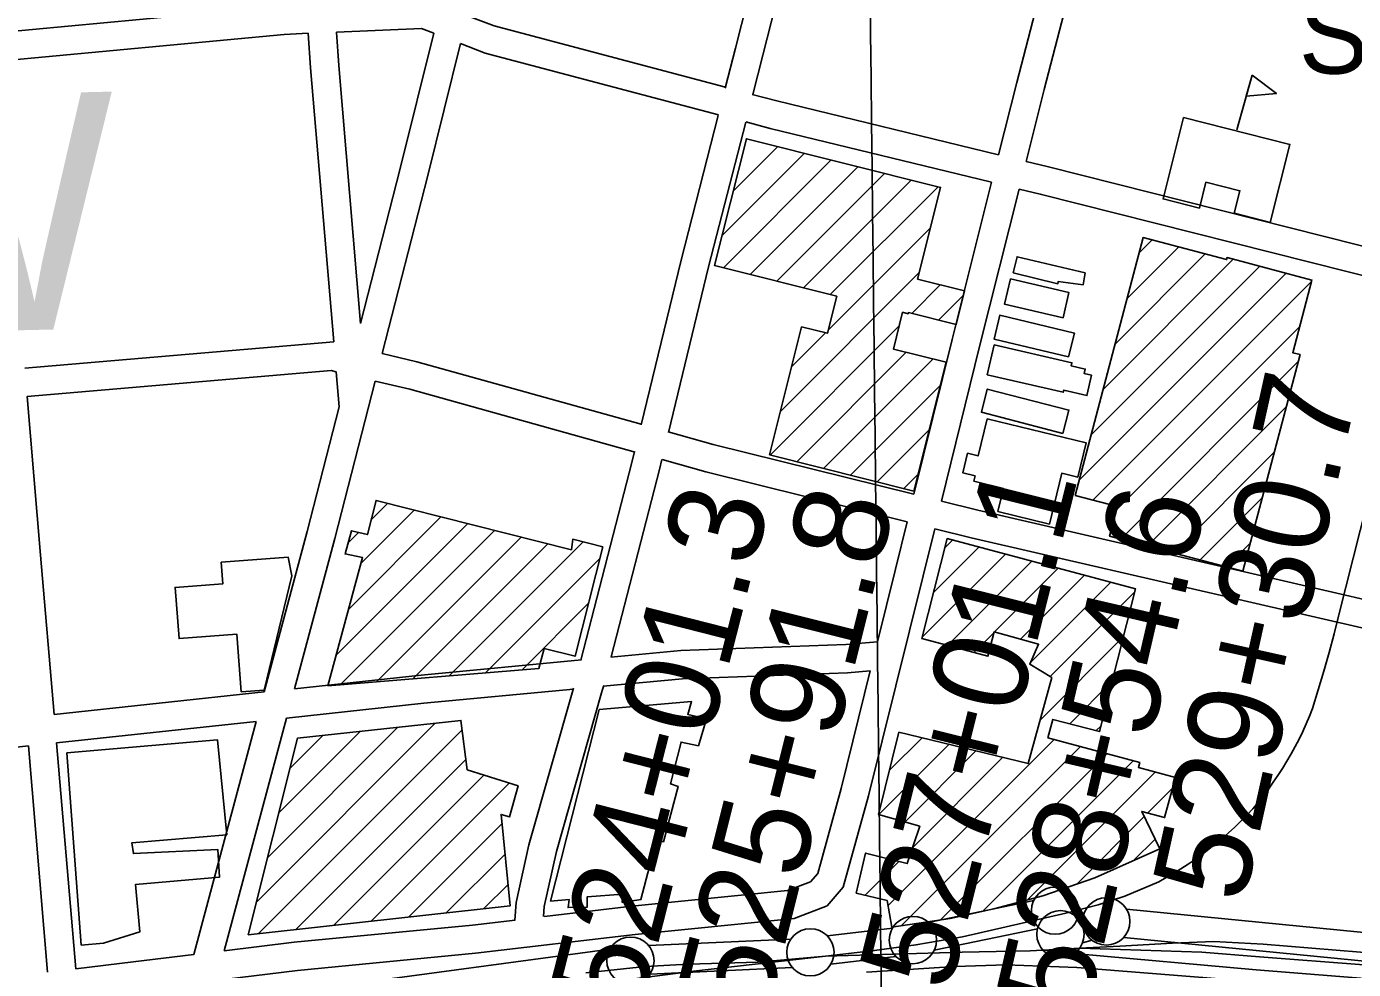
# Model space of a CAD drawing. Extents: x 3677843 to 3715951, y 511991 to 537744.
# Drawn here: x 3686291 to 3687695, y 533993 to 534990 of the extents above; entities that cross this region are included whole.
import ezdxf

# ---------------------------------------------------------------- set-up
doc = ezdxf.new("R2010")
doc.units = 0
for name, color, linetype in [('V-BLDG-IDEN', 7, 'Continuous'), ('V-BLDG-OTLN', 7, 'Continuous'), ('V-GRID-MAJR', 7, 'Continuous'), ('V-RAIL-TRAK', 7, 'Continuous'), ('V-ROAD-CNTR', 7, 'Continuous'), ('V-SURV-IDEN', 7, 'Continuous'), ('V-SURV-LINE', 7, 'Continuous'), ('V-TOPO-GNAM-IDEN', 7, 'Continuous')]:
    doc.layers.add(name, color=color, linetype=linetype)

msp = doc.modelspace()

# ---------------------------------------------------------------- linework, layer by layer
at = {"layer": 'V-BLDG-OTLN'}
for p, q in [((3687571.2611612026, 534880.8787085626), (3687587.2901291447, 534938.6975929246)), ((3687026.824611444, 534769.2415094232), (3687113.8029269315, 534856.2198249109)), ((3687038.658142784, 534816.430379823), (3687085.5365229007, 534863.3087599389)), ((3687028.0542040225, 534735.1157629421), (3687142.0693309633, 534849.1308898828)), ((3687056.3208279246, 534728.027047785), (3687170.335734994, 534842.0419548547)), ((3687084.5874518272, 534720.9383326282), (3687198.602139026, 534834.9530198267)), ((3687112.8540757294, 534713.8496174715), (3687226.868543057, 534827.8640847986)), ((3687141.120699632, 534706.7609023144), (3687255.1349470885, 534820.7751497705)), ((3687138.9757143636, 534669.2605779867), (3687247.1347835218, 534777.4196471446)), ((3687455.049351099, 534702.4915022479), (3687509.7499039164, 534757.192055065)), ((3687467.713929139, 534750.511419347), (3687481.773059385, 534764.570549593)), ((3687429.7201950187, 534606.4516680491), (3687567.4057363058, 534744.1372093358)), ((3687442.384773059, 534654.4715851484), (3687537.7267484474, 534749.8135605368)), ((3687088.422775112, 534583.3522996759), (3687235.298246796, 534730.2277713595)), ((3687404.3910389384, 534510.4118338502), (3687623.3595334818, 534729.3803283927)), ((3687417.0556169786, 534558.4317509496), (3687595.3826348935, 534736.7587688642)), ((3687227.3668848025, 534686.9410703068), (3687257.529902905, 534717.1040884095)), ((3687418.8377047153, 534489.5031605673), (3687650.4104398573, 534721.0758957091)), ((3687255.631909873, 534679.8507563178), (3687282.274512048, 534706.4933584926)), ((3687077.604196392, 534537.1783818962), (3687214.0337889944, 534673.6079744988)), ((3687444.0039970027, 534479.3141137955), (3687637.7455328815, 534673.0556496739)), ((3687100.257409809, 534630.5422734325), (3687136.058035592, 534666.342899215)), ((3687105.870501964, 534530.0893484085), (3687221.57390119, 534645.7927476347)), ((3687134.1368075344, 534523.0003149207), (3687249.839914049, 534638.7034214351)), ((3687448.3670056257, 534448.321783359), (3687636.120581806, 534636.0753595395)), ((3687162.403113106, 534515.9112814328), (3687257.596158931, 534611.1043272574)), ((3687476.3438063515, 534440.9432450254), (3687623.455619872, 534588.0550585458)), ((3687190.669418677, 534508.8222479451), (3687245.7617155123, 534563.91454478)), ((3687504.3206070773, 534433.5647066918), (3687610.790657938, 534540.0347575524)), ((3687218.935724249, 534501.733214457), (3687233.927272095, 534516.7247623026)), ((3686655.494295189, 534468.6218712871), (3686672.9273962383, 534486.0549723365)), ((3687532.2974078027, 534426.1861683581), (3687598.125696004, 534492.014456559)), ((3686631.57673944, 534373.993637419), (3686729.3770926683, 534471.7939906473)), ((3686644.7059794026, 534422.4782164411), (3686701.1522444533, 534478.924481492)), ((3686618.4474994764, 534325.5090583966), (3686757.601940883, 534464.6634998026)), ((3686622.643948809, 534294.3501686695), (3686785.826789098, 534457.5330089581)), ((3686631.1656525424, 534444.2932286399), (3686642.1418836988, 534455.2694597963)), ((3686661.1340708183, 534297.4849516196), (3686814.051637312, 534450.4025181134)), ((3686699.6241928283, 534300.6197345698), (3686842.276485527, 534443.2720272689)), ((3686738.1143148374, 534303.75451752), (3686879.653586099, 534445.2937887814)), ((3687262.1979648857, 534438.9294379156), (3687270.4722623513, 534447.2037353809)), ((3687560.2742085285, 534418.8076300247), (3687585.4607340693, 534443.9941555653)), ((3687238.123527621, 534344.1443225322), (3687326.3321141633, 534432.3529090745)), ((3687250.160746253, 534391.536880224), (3687298.4021882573, 534439.7783222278)), ((3686776.604436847, 534306.8893004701), (3686897.5312080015, 534427.8160716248)), ((3687265.2681762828, 534335.9336321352), (3687354.26204007, 534424.9274959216)), ((3687314.8076947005, 534350.1178114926), (3687382.191965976, 534417.5020827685)), ((3687342.4462611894, 534342.4010389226), (3687410.121891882, 534410.0766696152)), ((3687352.73641699, 534317.3358556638), (3687438.0518177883, 534402.6512564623)), ((3687373.709564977, 534302.9536645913), (3687463.089273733, 534392.333373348)), ((3686815.0945588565, 534310.0240834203), (3686885.481727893, 534380.4112524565)), ((3687293.086713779, 534328.3968305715), (3687314.3655457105, 534349.6756625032)), ((3687363.052896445, 534256.9416570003), (3687451.2570623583, 534345.1458229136)), ((3687394.396183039, 534252.9296045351), (3687439.424850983, 534297.9582724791)), ((3686534.2363084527, 534064.5211720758), (3686723.2871094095, 534253.5719730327)), ((3686536.0221206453, 534030.9516452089), (3686751.7551807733, 534246.684705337)), ((3686546.080325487, 534111.7205281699), (3686683.6508002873, 534249.29100297)), ((3687422.5455621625, 534245.7236445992), (3687427.5926396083, 534250.7707220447)), ((3686557.924342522, 534158.9198842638), (3686644.014491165, 534245.0100329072)), ((3686569.7683595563, 534206.1192403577), (3686604.3781820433, 534240.7290628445)), ((3687202.273724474, 534060.8071459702), (3687377.85077788, 534236.3841993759)), ((3687203.840381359, 534203.7951590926), (3687238.1893897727, 534238.1441675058)), ((3687192.4082789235, 534157.0077175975), (3687266.6264344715, 534231.2258731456)), ((3687216.1218276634, 534039.2999101), (3687405.709381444, 534228.8874638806)), ((3687219.8970534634, 534149.1411530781), (3687295.0634791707, 534224.3075787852)), ((3687257.861634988, 534045.6843783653), (3687433.567985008, 534221.390728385)), ((3686575.8080925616, 534035.3822780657), (3686755.7368139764, 534215.3109994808)), ((3687228.352094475, 534122.2408550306), (3687323.5005238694, 534217.3892844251)), ((3687302.1520817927, 534054.6194861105), (3687461.4265885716, 534213.8939928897)), ((3686615.594064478, 534039.8129109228), (3686774.577562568, 534198.7964090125)), ((3686655.3800363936, 534044.2435437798), (3686801.3983208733, 534190.2618282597)), ((3687349.7251066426, 534066.837171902), (3687484.8869513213, 534201.9990165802)), ((3687476.931508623, 534158.6882348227), (3687503.1022089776, 534184.8589351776)), ((3686801.2301170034, 534154.7382853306), (3686801.947162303, 534155.4553306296)), ((3687401.800874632, 534083.5576008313), (3687473.219150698, 534154.9758768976)), ((3686695.1660083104, 534048.674176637), (3686793.8609017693, 534147.369070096)), ((3687461.910575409, 534108.3119625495), (3687484.697111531, 534131.0984986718)), ((3686734.9519802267, 534053.1048094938), (3686797.117988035, 534115.2708173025)), ((3687177.9519670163, 534071.8407275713), (3687213.5165841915, 534107.4053447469)), ((3686774.737952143, 534057.5354423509), (3686800.375074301, 534083.1725645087))]:
    msp.add_line(p, q, dxfattribs=at)
for points in [[(3687587.2901291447, 534938.6975929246), (3687613.114077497, 534919.5526312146), (3687581.118141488, 534916.4356374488)], [(3687514.9409312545, 534894.044185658), (3687627.3287064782, 534865.5802425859), (3687606.441748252, 534783.1114075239), (3687568.385824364, 534792.749388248), (3687574.4178123, 534816.56834061), (3687538.525884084, 534825.6573224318), (3687531.575897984, 534798.2133773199), (3687493.1369748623, 534807.9483578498)], [(3687076.8880000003, 534537.358), (3687110.823, 534672.672), (3687138.115, 534665.827), (3687147.947, 534705.049), (3687018.846, 534737.425), (3687052.492, 534871.596), (3687257.839, 534820.0970000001), (3687233.517, 534723.126), (3687283.3140000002, 534710.638), (3687274.411, 534675.14), (3687223.8910000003, 534687.813), (3687223.588, 534686.602), (3687217.665, 534688.087), (3687207.917, 534649.218), (3687263.649, 534635.24), (3687229.503, 534499.083)], [(3687400.1750000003, 534494.426), (3687472.095, 534767.123), (3687560.441, 534743.823), (3687560.972, 534745.834), (3687650.699, 534722.17), (3687630.44, 534645.356), (3687638.04, 534643.353), (3687577.612, 534414.235), (3687436.65, 534451.412), (3687444.879, 534482.634)], [(3687408.832, 534716.984), (3687382.341, 534720.794), (3687381.983, 534718.289), (3687334.772, 534729.819), (3687338.674, 534746.8150000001), (3687410.651, 534729.643)], [(3687387.469, 534682.183), (3687325.603, 534696.4940000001), (3687331.8030000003, 534723.2880000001), (3687393.642, 534708.86)], [(3687393.304, 534640.8640000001), (3687314.435, 534659.757), (3687320.483, 534685.005), (3687399.344, 534666.083)], [(3687314.495, 534653.654), (3687396.755, 534634.794), (3687395.983, 534631.425), (3687410.89, 534628.007), (3687409.79, 534623.206), (3687417.54, 534621.429), (3687412.643, 534600.074), (3687388.1, 534605.7), (3687387.6, 534603.525), (3687307.2290000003, 534621.953)], [(3687387.3200000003, 534560.091), (3687300.9560000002, 534582.3), (3687307.267, 534606.841), (3687393.628, 534584.63)], [(3687307.126, 534575.578), (3687411.832, 534550.16), (3687402.983, 534513.706), (3687385.9930000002, 534517.831), (3687372.98, 534464.23), (3687318.4560000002, 534477.469), (3687324.3910000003, 534501.922), (3687292.913, 534509.563), (3687294.25, 534515.062), (3687281.381, 534518.185), (3687286.437, 534539.001), (3687297.591, 534536.291)], [(3686900.619, 534439.964), (3686871.236, 534324.366), (3686838.417, 534332.706), (3686833.02, 534311.484), (3686609.725, 534293.2980000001), (3686646.3740000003, 534428.638), (3686628.022, 534432.527), (3686634.563, 534457.009), (3686651.559, 534453.108), (3686660.7, 534489.144), (3686867.412, 534436.922), (3686868.733, 534448.0700000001)], [(3687371.222, 534238.1680000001), (3687468.4760000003, 534211.997), (3687467.075, 534206.7930000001), (3687506.173, 534196.27), (3687494.768, 534153.889), (3687470.6180000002, 534160.387), (3687489.7260000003, 534120.637), (3687420.841, 534090.1140000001), (3687366.088, 534071.26), (3687313.997, 534057.18), (3687267.973, 534047.231), (3687206.342, 534037.804), (3687201.312, 534066.245), (3687168.679, 534074.062), (3687178.436, 534116.212), (3687222.636, 534105.116), (3687235.811, 534144.587), (3687192.278, 534157.045), (3687213.8030000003, 534244.077), (3687350.466, 534210.829), (3687375.343, 534301.9670000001), (3687352.1410000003, 534315.982), (3687361.429, 534337.101), (3687314.4990000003, 534350.204), (3687307.972, 534324.3640000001), (3687237.92, 534343.343), (3687264.69, 534448.741), (3687463.95, 534395.7660000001), (3687426.099, 534244.814), (3687376.433, 534257.528)], [(3686517.958, 534286.753), (3686513.287, 534347.752), (3686452.34, 534343.083), (3686448.197, 534397.201), (3686498.639, 534401.064), (3686496.903, 534423.756), (3686567.647, 534429.175), (3686571.6890000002, 534409.373), (3686542.3850000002, 534288.623)], [(3686845.222, 534065.446), (3686896.807, 534268.081), (3686994.399, 534276.505), (3686990.4620000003, 534262.902), (3687010.176, 534258.3470000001), (3687001.642, 534229.775), (3686983.29, 534233.664), (3686972.194, 534189.4670000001), (3686980.36, 534186.833), (3686964.6580000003, 534128.348), (3686957.1780000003, 534130.306), (3686940.843, 534067.064), (3686921.203, 534064.16), (3686921.795, 534072.983), (3686883.841, 534069.894), (3686883.946, 534059.046), (3686863.875, 534058.575), (3686864.971, 534067.0430000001)], [(3686525.519, 534029.782), (3686577.731, 534237.851), (3686750.508, 534256.512), (3686757.128, 534204.349), (3686810.879, 534187.245), (3686801.7060000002, 534154.5970000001), (3686792.861, 534157.223), (3686802.661, 534060.645)], [(3686348.623, 534018.862), (3686333.73, 534222.2), (3686492.9930000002, 534235.981), (3686502.799, 534135.6900000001), (3686402.4960000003, 534127.24), (3686403.966, 534115.724), (3686493.458, 534119.998), (3686495.1, 534090.8470000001), (3686406.322, 534083.1900000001), (3686410.887, 534033.042), (3686372.341, 534021.131)]]:
    msp.add_lwpolyline(points, close=True, dxfattribs=at)
at = {"layer": 'V-GRID-MAJR'}
msp.add_spline([(3687380.148, 517465.955), (3687312.292, 523524.615), (3687244.413, 529585.207), (3687176.535, 535645.813), (3687176.514, 535647.732)], degree=3, dxfattribs=at)
at = {"layer": 'V-RAIL-TRAK'}
for points in [[(3686882.6720000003, 533989.645), (3686945.636, 533996.432), (3686990.829, 533998.935), (3687064.799, 534001.034), (3687135.989, 534007.2170000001), (3687187.998, 534013.21), (3687231.786, 534019.122), (3687281.029, 534027.83), (3687390.398, 534052.888), (3687424.569, 534061.446), (3687452.569, 534070.627), (3687488.7260000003, 534086.057), (3687496.628, 534090.401), (3687504.4220000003, 534094.935), (3687512.106, 534099.656), (3687519.6720000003, 534104.561), (3687527.1180000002, 534109.65), (3687534.438, 534114.915), (3687541.628, 534120.357), (3687548.686, 534125.97), (3687555.6040000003, 534131.754), (3687562.381, 534137.701), (3687569.012, 534143.813), (3687575.494, 534150.082), (3687581.822, 534156.506), (3687587.9930000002, 534163.082), (3687593.684, 534169.884), (3687599.2120000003, 534176.822), (3687604.565, 534183.894), (3687609.747, 534191.095), (3687614.748, 534198.42), (3687619.573, 534205.867), (3687624.214, 534213.428), (3687628.666, 534221.1), (3687632.932, 534228.88), (3687637.008, 534236.761), (3687640.887, 534244.74), (3687644.571, 534252.813), (3687648.059, 534260.973), (3687651.346, 534269.214), (3687657.377, 534288.862), (3687663.173, 534308.582), (3687668.735, 534328.372), (3687674.058, 534348.228), (3687678.787, 534366.7440000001), (3687679.143, 534368.144), (3687716.724, 534517.181)], [(3687135.989, 534007.2170000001), (3687280.504, 534011.383), (3687352.4280000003, 534012.777), (3687366.068, 534013.5), (3687405.301, 534015.581), (3687447.6070000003, 534017.828), (3687503.069, 534021.115), (3687546.898, 534022.917), (3687598.995, 534020.005), (3687701.845, 534011.428), (3687826.6240000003, 534002.382), (3687881.48, 533997.442), (3687962.4080000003, 533988.65)], [(3688853.471, 533806.042), (3688771.809, 533819.6240000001), (3688502.761, 533869.039), (3688469.424, 533874.4720000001), (3688431.394, 533880.667), (3688317.4620000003, 533901.4670000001), (3688176.093, 533925.42), (3687987.384, 533956.4450000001), (3687929.0670000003, 533964.776), (3687859.12, 533971.623), (3687790.555, 533977.112), (3687591.716, 533992.963), (3687403.159, 534009.748), (3687366.068, 534013.5)], [(3687405.301, 534015.581), (3687534.143, 534011.373), (3687595.165, 534006.492), (3687705.5500000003, 533997.991), (3687788.523, 533990.587), (3687866.691, 533983.823), (3687916.744, 533979.52), (3687951.044, 533975.064), (3687998.3880000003, 533967.9940000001), (3688073.191, 533955.03), (3688174.073, 533937.526), (3688336.725, 533908.987), (3688471.639, 533885.947), (3688603.109, 533863.495)], [(3687135.989, 534007.2170000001), (3686996.383, 533991.454), (3686808.219, 533966.988), (3686563.964, 533933.7490000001), (3686254.7120000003, 533891.648), (3686079.573, 533866.626), (3686020.077, 533855.763), (3685970.161, 533845.679), (3685928.49, 533833.623), (3685839.875, 533810.277)], [(3687179.3170000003, 533990.518), (3687273.119, 533996.238), (3687327.223, 533998.142), (3687401.926, 533995.453), (3687552.769, 533983.2390000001)]]:
    msp.add_lwpolyline(points, dxfattribs=at)
at = {"layer": 'V-ROAD-CNTR'}
for points in [[(3687030.0109782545, 534925.182304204), (3687040.81027131, 534967.3160175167), (3687104.7795540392, 535219.3801315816), (3687113.6664408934, 535254.030464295)], [(3687059.2383254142, 534918.384280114), (3687069.8797286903, 534959.9019824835), (3687133.8484459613, 535211.9638684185), (3687142.2266597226, 535244.6308640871)], [(3687319.140322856, 534854.5992645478), (3687338.366284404, 534931.141111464), (3687393.77317359, 535144.619684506), (3687402.78815556, 535178.736616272)], [(3687348.2922645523, 534847.5122787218), (3687367.434226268, 534923.719126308), (3687422.7951155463, 535137.0196997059), (3687431.97309719, 535171.7536302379)], [(3686259.20544273, 534983.5570066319), (3686561.3428384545, 535011.858950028), (3686586.946787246, 535012.9809477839)], [(3686757.4064463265, 535001.6519704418), (3686785.540390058, 534990.8059921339), (3687030.1784113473, 534926.0362458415)], [(3686261.726437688, 534953.662066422), (3686563.398834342, 534981.9210099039), (3686588.95978322, 534983.0410076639)], [(3686615.878729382, 534656.702660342), (3686591.4027783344, 534946.686080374), (3686588.95978322, 534983.0400076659)], [(3686618.938723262, 534984.354005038), (3686708.67454379, 534988.285997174), (3686721.9065173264, 534983.185007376)], [(3686644.3336724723, 534676.2656212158), (3686621.3187185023, 534948.9540758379), (3686618.9397232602, 534984.354005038)], [(3686644.3336724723, 534676.2656212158), (3686686.337588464, 534840.0332936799), (3686721.9065173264, 534983.185007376)], [(3686667.148626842, 534644.4606848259), (3686715.425530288, 534832.689308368), (3686750.116460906, 534972.3090291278)], [(3686750.115460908, 534972.3100291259), (3686776.278408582, 534962.2240492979), (3687023.0757874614, 534896.8835923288)], [(3687058.6226743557, 534918.5054144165), (3687084.794791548, 534911.576150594), (3687319.141322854, 534854.6012645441)], [(3686941.0881707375, 534569.030098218), (3686983.3959314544, 534743.3305729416), (3687022.549028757, 534896.0703353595)], [(3686970.042390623, 534561.1328407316), (3687012.504068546, 534736.0674270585), (3687051.6978048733, 534888.9657259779)], [(3687051.761720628, 534889.2888926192), (3687077.4108063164, 534882.49820875), (3687311.832337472, 534825.5043227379)], [(3687348.2922645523, 534847.514278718), (3687370.460220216, 534842.1242894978), (3687736.6574878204, 534749.7094743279), (3688044.073872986, 534673.1546274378)], [(3687229.671501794, 534495.6569824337), (3687270.052421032, 534659.1686554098), (3687311.832337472, 534825.5033227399)], [(3687258.7854435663, 534488.4189969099), (3687299.162362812, 534651.9186699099), (3687340.9842791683, 534818.4163369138)], [(3687340.98327917, 534818.4173369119), (3687363.246234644, 534813.004347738), (3687729.361502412, 534720.609532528), (3688036.979887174, 534644.005685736)], [(3686289.1113829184, 534629.042715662), (3686615.878729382, 534656.702660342)], [(3686667.148626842, 534644.4606848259), (3686703.7575536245, 534635.789702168), (3686940.9628473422, 534569.7154185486)], [(3686291.6323778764, 534599.14877545), (3686613.3237344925, 534626.3787209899), (3686618.5427240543, 534625.1437234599)], [(3686621.6827177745, 534587.9427978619), (3686618.5427240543, 534625.1437234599)], [(3686574.3458124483, 534290.0913935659), (3686616.958727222, 534448.7720762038), (3686659.6936417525, 534615.395742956)], [(3686659.6936417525, 534615.395742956), (3686696.271568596, 534606.7317602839), (3686934.8575678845, 534540.2739666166)], [(3686291.6333778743, 534599.1497754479), (3686305.8003495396, 534431.2031113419), (3686320.178320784, 534262.7194483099)], [(3686542.3578764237, 534286.646400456), (3686587.9407852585, 534456.3900609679), (3686621.6827177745, 534587.9427978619)], [(3686969.8311669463, 534561.6740569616), (3687017.294926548, 534548.452876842), (3687229.671501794, 534495.6579824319)], [(3686877.375998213, 534320.2750291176), (3686931.3908579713, 534529.0807408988), (3686934.2454848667, 534540.8403736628)], [(3686909.256502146, 534323.7270674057), (3686960.491142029, 534521.7852591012), (3686963.0630361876, 534532.380174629)], [(3686963.2974682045, 534532.3520724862), (3687009.64894184, 534519.440934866), (3687222.47851618, 534466.5330406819)], [(3687258.7844435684, 534488.4199969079), (3687297.196366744, 534478.871016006), (3687724.12251289, 534380.267213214), (3687956.629047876, 534321.9293298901)], [(3686181.54559805, 533944.5300846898), (3686407.21014672, 533971.4420308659), (3686577.437806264, 533992.2319892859), (3686765.8674294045, 534010.3469530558), (3686934.673091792, 534030.2769131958), (3687102.9177553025, 534047.266879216), (3687137.720685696, 534060.5488526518), (3687154.937651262, 534080.17981339), (3687181.716597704, 534176.9086199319), (3687239.2634826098, 534409.3721550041), (3687251.592457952, 534459.2940551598)], [(3687191.0855789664, 534339.5962945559), (3687210.1415408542, 534416.572140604), (3687222.47851618, 534466.532040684)], [(3687251.592457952, 534459.2950551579), (3687290.202380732, 534449.6970743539), (3687717.096526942, 534351.1012715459), (3687948.6550638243, 534293.000387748)], [(3686908.901486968, 534323.5805628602), (3686982.996995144, 534330.6213125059), (3687157.5526460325, 534336.648300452), (3687191.084578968, 534339.597294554)], [(3686574.3448124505, 534290.092393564), (3686708.29454455, 534304.518364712), (3686877.8735155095, 534320.6322035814)], [(3686838.777969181, 534049.1634626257), (3686931.407098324, 534060.0988535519), (3687095.941769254, 534076.7148203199), (3687120.0727209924, 534085.9248018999), (3687127.8577054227, 534094.7997841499), (3687152.6946557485, 534184.5166047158), (3687183.4645942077, 534308.8113561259)], [(3686901.087000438, 534292.7034919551), (3686984.9349912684, 534300.6713724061), (3687159.384642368, 534306.6943603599), (3687183.4645942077, 534308.8113561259)], [(3686566.000829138, 534259.020455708), (3686711.320538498, 534274.6704244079), (3686869.5842794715, 534289.709861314)], [(3686807.645006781, 534045.4880408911), (3686808.878469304, 534063.903202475), (3686822.3313239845, 534125.1832997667), (3686869.5051607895, 534290.5343256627)], [(3686837.9518783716, 534049.0659379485), (3686838.661530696, 534059.660797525), (3686851.4346760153, 534117.8447002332), (3686899.337614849, 534285.7513327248), (3686900.3605837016, 534289.3380383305), (3686901.4662415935, 534293.612189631)], [(3686320.1773207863, 534262.7184483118), (3686542.356876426, 534286.6474004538)], [(3686322.7283156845, 534232.8205081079), (3686534.0128931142, 534255.5754625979)], [(3686467.81502551, 534009.0659556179), (3686534.013893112, 534255.5744626)], [(3686499.931961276, 534012.9889477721), (3686566.001829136, 534259.01945571)], [(3686322.7293156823, 534232.8205081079), (3686343.1072749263, 533994.0099857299)], [(3686254.4124523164, 534225.4625228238), (3686292.894375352, 534229.607514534)], [(3686292.894375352, 534229.607514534), (3686313.3023345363, 533990.4549928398)], [(3686499.9309612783, 534012.9889477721), (3686574.183812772, 534022.0579296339), (3686762.673435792, 534040.1788933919), (3686807.6871959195, 534045.4930215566)], [(3686343.1072749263, 533994.0099857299), (3686403.616153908, 534001.225971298), (3686467.81502551, 534009.066955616)]]:
    msp.add_lwpolyline(points, dxfattribs=at)
at = {"layer": 'V-SURV-LINE'}
for points in [[(3687245.0966443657, 534043.0650218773), (3687356.3326940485, 534066.0580020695)], [(3687403.602953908, 534051.3197552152), (3687409.896032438, 534053.0878846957)], [(3687454.534430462, 534057.0271802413), (3687964.0611848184, 534007.000549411)], [(3687138.180323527, 534028.6257420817), (3687206.9325337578, 534036.8503944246)], [(3687360.3598112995, 534036.2562277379), (3687251.1893600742, 534013.6902158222)], [(3686949.0838261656, 534018.4043001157), (3687099.465278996, 534025.4124399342)], [(3687418.0187385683, 534024.2084505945), (3687407.937796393, 534021.3760672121)], [(3687961.123077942, 533977.1447698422), (3687451.5957678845, 534027.1714552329)], [(3686321.8887342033, 533935.6323531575), (3686908.0042311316, 534014.6842418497)], [(3687100.8557908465, 533995.4446820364), (3686950.4750792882, 533988.4365767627)], [(3687210.5165639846, 534007.0652444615), (3687141.7652391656, 533998.8406980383)]]:
    msp.add_lwpolyline(points, dxfattribs=at)
for centre in [(3687378.9505000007, 534055.41592), (3687433.18699, 534044.05126), (3687384.647070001, 534030.41325), (3687120.1262, 534011.3589000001), (3687228.571170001, 534024.33156), (3686929.813810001, 534002.48957)]:
    msp.add_circle(centre, 25, dxfattribs=at)

# ---------------------------------------------------------------- texts
at = {"layer": 'V-BLDG-IDEN'}
msp.add_text('Sch.', height=82.99983200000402, dxfattribs=at).set_placement((3687636.63268787, 534940.412092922))
at = {"layer": 'V-SURV-IDEN'}
for s, height, rotation, p in [('   529+30.7   ', 100, 77.47622098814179, (3687554.1433259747, 533952.3633810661)), ('   524+01.3   ', 99.99999999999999, 75.72443992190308, (3686912.031851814, 533835.6804428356)), ('   525+91.8   ', 100.0000000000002, 75.96898344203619, (3687046.9811474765, 533833.7655073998)), ('   527+01.1   ', 99.99999999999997, 75.99345775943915, (3687240.186306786, 533859.4898384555)), ('   528+54.6   ', 100, 76.93933782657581, (3687387.4458551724, 533833.2380898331))]:
    msp.add_text(s, height=height, rotation=rotation, dxfattribs=at).set_placement(p)
at = {"layer": 'V-TOPO-GNAM-IDEN'}
msp.add_text('NEW', height=249.99950199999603, rotation=1.3443137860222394, dxfattribs=at).set_placement((3685608.43174428, 534653.199667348))

doc.saveas('drawing.dxf')
